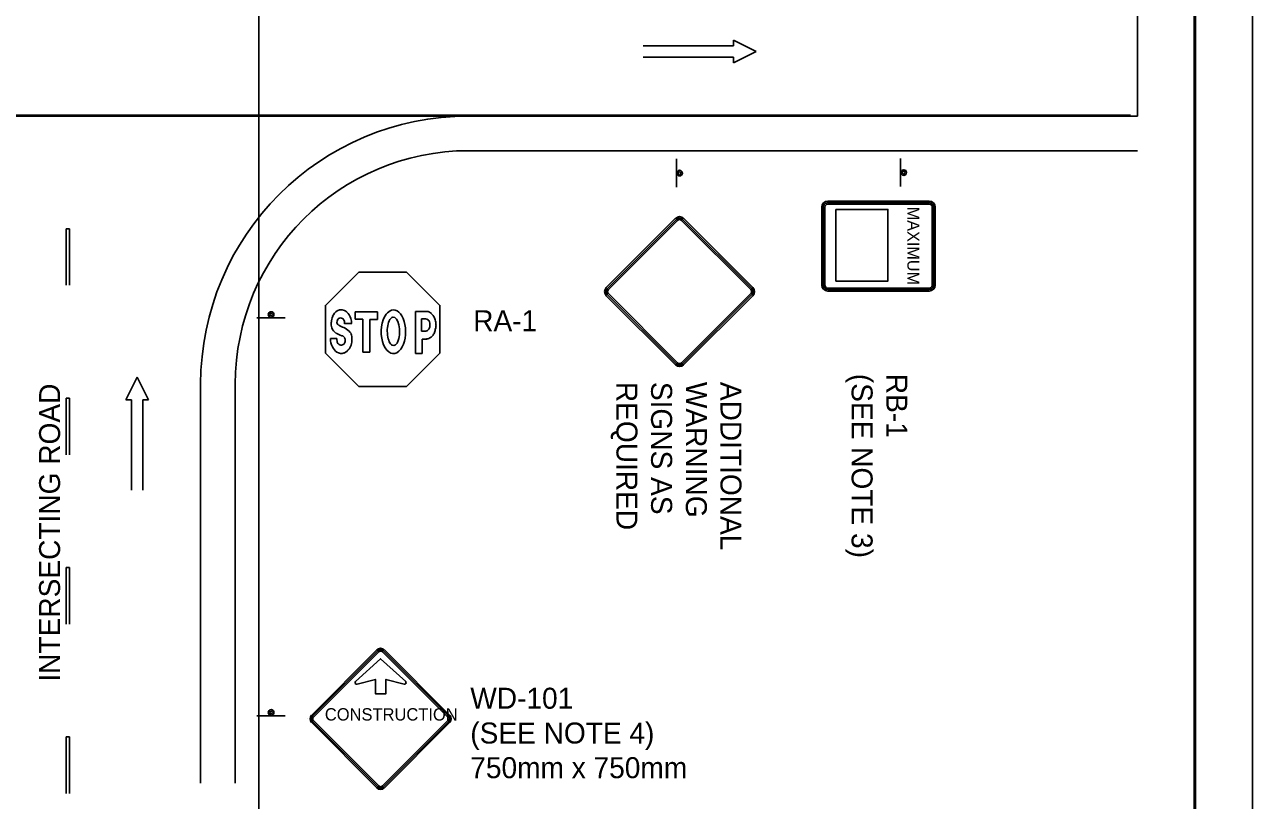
# Model space of a CAD drawing. Extents: x 1373 to 1583, y 130 to 399.
# Drawn here: x 1477.8 to 1583.1, y 197.4 to 263.9 of the extents above; entities that cross this region are included whole.
import ezdxf

# ---------------------------------------------------------------- set-up
doc = ezdxf.new("R2010")
doc.units = 0
for name, color, linetype in [('Level 10', 7, 'Continuous'), ('Level 17', 7, 'Continuous'), ('Level 18', 7, 'Continuous'), ('Level 2', 7, 'Continuous'), ('Level 60', 7, 'Continuous')]:
    doc.layers.add(name, color=color, linetype=linetype)

msp = doc.modelspace()

# ---------------------------------------------------------------- linework, layer by layer
at = {"layer": 'Level 10'}
for p, q in [((1497.88, 390.01), (1497.88, 138.3)), ((1538.57, 262.54), (1540.51, 261.58)), ((1538.57, 262.06), (1538.57, 262.54)), ((1530.83, 262.06), (1538.57, 262.06)), ((1538.57, 261.09), (1530.83, 261.09)), ((1540.51, 261.58), (1538.57, 260.61)), ((1538.57, 260.61), (1538.57, 261.09)), ((1572.59, 256.13), (1394.25, 256.13)), ((1573.19, 256.04), (1515.85, 256.04)), ((1573.19, 253.08), (1515.85, 253.08)), ((1506.12, 238.64), (1506.12, 239.27)), ((1506.12, 239.27), (1508.03, 239.27)), ((1508.03, 239.27), (1508.03, 238.62)), ((1509.38, 239.43), (1509.4, 239.43)), ((1511.29, 235.71), (1511.29, 239.3)), ((1511.29, 239.3), (1512.29, 239.3)), ((1505.83, 238.26), (1505.21, 238.26)), ((1506.78, 238.64), (1506.12, 238.64)), ((1506.78, 235.82), (1506.78, 238.64)), ((1508.03, 238.62), (1507.4, 238.62)), ((1507.4, 238.62), (1507.4, 235.82)), ((1509.35, 238.82), (1509.38, 238.82)), ((1511.81, 238.66), (1511.81, 237.61)), ((1512.2, 238.66), (1511.81, 238.66)), ((1512.2, 238.66), (1511.81, 238.66)), ((1511.81, 238.66), (1511.81, 237.61)), ((1504.01, 236.98), (1504.57, 236.98)), ((1511.81, 237.61), (1512.19, 237.61)), ((1511.81, 237.61), (1512.19, 237.61)), ((1512.24, 236.94), (1511.88, 236.93)), ((1511.88, 236.93), (1512.26, 236.93)), ((1511.88, 236.93), (1511.88, 235.71)), ((1504.18, 236.26), (1504.18, 236.27)), ((1507.4, 235.82), (1506.78, 235.82)), ((1511.88, 235.71), (1511.29, 235.71)), ((1486.47, 231.73), (1487.44, 233.66)), ((1487.44, 233.66), (1488.4, 231.73)), ((1492.88, 233.08), (1492.88, 198.88)), ((1495.85, 233.08), (1495.85, 198.88)), ((1486.95, 231.73), (1486.47, 231.73)), ((1486.95, 223.99), (1486.95, 231.73)), ((1488.4, 231.73), (1487.92, 231.73)), ((1487.92, 231.73), (1487.92, 223.99))]:
    msp.add_line(p, q, dxfattribs=at)
for points in [[(1573.19, 279.61), (1573.19, 256.04), (1394.01, 256.04), (1394.01, 279.61)], [(1513.4, 235.73), (1510.53, 232.87), (1506.45, 232.87), (1503.58, 235.73), (1503.58, 239.82), (1506.45, 242.68), (1510.53, 242.68), (1513.4, 239.82)]]:
    msp.add_lwpolyline(points, close=True, dxfattribs=at)
for centre, radius, start, end in [((1515.85, 233.08), 22.97, 90, 180), ((1515.85, 233.08), 20, 90, 180), ((1505.19, 238.44), 1.09, 123.3662, 155.6734), ((1504.94, 238.78), 0.665, 46.1369, 121.3987), ((1504.67, 238.41), 1.12, 14.564, 49.0063), ((1512.24, 238.71), 0.596, 44.8528, 85.0441), ((1512.05, 238.45), 0.915, 29.2241, 48.5308), ((1512.05, 238.45), 0.915, 29.2241, 48.5308), ((1505.42, 238.26), 1.34, 174.8171, 195.9183), ((1505.61, 238.31), 1.52, 157.7332, 177.1392), ((1504.87, 238.38), 0.302, 164.131, 238.1476), ((1504.91, 238.43), 0.331, 113.8064, 172.2407), ((1505.83, 239.9), 2.1, 237.9816, 250.979), ((1504.89, 238.4), 0.346, 47.3017, 109.0119), ((1504.72, 238.34), 0.506, 350.4412, 39.3244), ((1504.6, 236.56), 1.47, 46.2465, 67.9263), ((1504.27, 238.24), 1.55, 0.6952, 17.1452), ((1512.14, 238.32), 0.354, 35.1198, 79.3117), ((1512.14, 238.32), 0.354, 35.1198, 79.3117), ((1511.98, 238.21), 0.55, 8.6031, 34.217), ((1511.98, 238.21), 0.55, 8.6031, 34.217), ((1512.01, 238.07), 0.522, 326.5086, 357.0313), ((1512.01, 238.07), 0.522, 326.5086, 357.0313), ((1511.96, 238.14), 0.585, 350.3417, 15.2342), ((1511.96, 238.14), 0.585, 350.3417, 15.2342), ((1512.04, 238.36), 0.972, 13.0674, 33.762), ((1511.17, 238.07), 1.89, 3.3903, 15.6597), ((1511.54, 238.11), 1.52, 349.7521, 2.7916), ((1511.54, 238.11), 1.52, 349.7521, 2.7916), ((1505.88, 237.06), 1.88, 182.3841, 204.9519), ((1505.03, 238.22), 0.952, 200.4481, 235.1107), ((1507.47, 243.66), 6.9, 244.4624, 248.8312), ((1505.42, 236.97), 0.856, 179.0172, 193.5172), ((1504.87, 236.81), 0.435, 34.2083, 74.1552), ((1504.88, 236.85), 0.399, 352.5761, 30.4776), ((1507.6, 239.24), 2.57, 219.479, 223.4261), ((1504.33, 236.89), 1.53, 5.9097, 21.9865), ((1503.69, 236.89), 2.16, 351.247, 3.9864), ((1512.11, 238.01), 0.406, 281.9191, 325.7868), ((1512.11, 238.01), 0.406, 281.9191, 325.7868), ((1512.28, 237.15), 0.207, 259.7909, 293.5419), ((1512.1, 237.8), 0.882, 286.602, 299.8091), ((1512.28, 237.57), 0.597, 295.3838, 322.6188), ((1512.03, 237.85), 0.968, 318.2922, 338.6031), ((1512.03, 237.85), 0.968, 318.2922, 338.6031), ((1511.08, 238.23), 1.98, 338.3153, 348.6699), ((1505.36, 236.9), 1.34, 208.4154, 233.6553), ((1504.94, 236.31), 0.612, 232.0536, 292.7397), ((1505.01, 236.8), 0.43, 186.8728, 222.7449), ((1504.96, 236.84), 0.419, 230.6966, 271.4573), ((1504.93, 236.81), 0.388, 275.4374, 314.0625), ((1504.8, 236.64), 0.977, 293.1413, 324.9906), ((1504.76, 236.81), 0.516, 326.253, 358.7323), ((1504.2, 237.04), 1.7, 325.5092, 343.2894)]:
    msp.add_arc(centre, radius, start, end, dxfattribs=at)
for centre, major_axis, ratio, start_param, end_param in [((1509.41, 237.56), (-0.01, -1.87), 0.558644, 3.185857, 4.129398), ((1509.41, 237.56), (-0.01, -1.87), 0.558644, 0.656861, 3.168126), ((1509.41, 237.56), (-0.01, -1.87), 0.558644, 4.129576, 6.939747), ((1509.41, 237.6), (0.01, -1.22), 0.432619, 3.890436, 7.165085), ((1509.41, 237.6), (0.01, -1.22), 0.432619, 3.239639, 3.888884), ((1509.41, 237.6), (0.01, -1.22), 0.432619, 0.881967, 3.190734)]:
    msp.add_ellipse(centre, major_axis=major_axis, ratio=ratio, start_param=start_param, end_param=end_param, dxfattribs=at)
at = {"layer": 'Level 17'}
for p, q in [((1533.67, 252.38), (1533.67, 249.96)), ((1552.89, 252.41), (1552.89, 250)), ((1546.65, 248.75), (1555.35, 248.75)), ((1546.65, 248.62), (1555.35, 248.62)), ((1546.65, 248.5), (1555.35, 248.5)), ((1555.76, 248.47), (1555.76, 248.47)), ((1546.14, 241.57), (1546.14, 248.24)), ((1546.27, 241.57), (1546.27, 248.24)), ((1546.4, 241.57), (1546.4, 248.24)), ((1555.61, 248.24), (1555.61, 241.57)), ((1555.74, 248.24), (1555.74, 241.57)), ((1555.82, 248.36), (1555.81, 248.36)), ((1555.86, 248.24), (1555.86, 241.57)), ((1555.87, 248.24), (1555.86, 248.24)), ((1527.66, 241.35), (1533.59, 247.29)), ((1527.75, 241.27), (1533.68, 247.19)), ((1527.84, 241.18), (1533.77, 247.1)), ((1534.11, 247.1), (1540.04, 241.18)), ((1534.2, 247.19), (1540.13, 241.27)), ((1534.29, 247.29), (1540.21, 241.35)), ((1555.35, 241.31), (1546.65, 241.31)), ((1555.35, 241.18), (1546.65, 241.18)), ((1533.59, 234.73), (1527.66, 240.65)), ((1533.68, 234.81), (1527.75, 240.74)), ((1533.77, 234.9), (1527.84, 240.83)), ((1540.04, 240.83), (1534.11, 234.9)), ((1540.12, 240.74), (1534.2, 234.81)), ((1540.21, 240.65), (1534.29, 234.73)), ((1540.04, 240.83), (1540.04, 240.83)), ((1540.13, 240.74), (1540.12, 240.74)), ((1540.22, 240.65), (1540.21, 240.65)), ((1555.35, 241.05), (1546.65, 241.05)), ((1497.7, 238.76), (1500.12, 238.76)), ((1502.4, 204.71), (1508, 210.3)), ((1502.48, 204.62), (1508.08, 210.22)), ((1502.56, 204.54), (1508.17, 210.14)), ((1508.46, 210.14), (1514.06, 204.54)), ((1508.55, 210.22), (1514.15, 204.62)), ((1508.63, 210.3), (1514.23, 204.71)), ((1506.29, 207.36), (1506.29, 207.36)), ((1506.29, 207.36), (1506.29, 207.36)), ((1506.29, 207.36), (1506.29, 207.36)), ((1497.7, 204.66), (1500.12, 204.66)), ((1502.08, 204.39), (1502.08, 204.39)), ((1508.17, 198.64), (1502.56, 204.24)), ((1514.06, 204.24), (1508.46, 198.64)), ((1508, 198.47), (1502.4, 204.07)), ((1508.08, 198.56), (1502.48, 204.16)), ((1514.15, 204.16), (1508.55, 198.56)), ((1514.23, 204.07), (1508.63, 198.47))]:
    msp.add_line(p, q, dxfattribs=at)
msp.add_lwpolyline([(1547.35, 248.05), (1551.8, 248.05), (1551.8, 241.91), (1547.35, 241.91)], close=True, dxfattribs=at)
for points in [[(1506.17, 207.59), (1508.31, 209.54), (1510.46, 207.59)], [(1506.17, 207.59), (1508.31, 209.54), (1510.46, 207.59)], [(1506.17, 207.59), (1508.31, 209.54), (1510.46, 207.59)], [(1510.33, 207.36), (1508.76, 207.77), (1508.76, 206.54), (1507.87, 206.54), (1507.87, 207.77), (1506.29, 207.36)], [(1510.33, 207.36), (1508.76, 207.77), (1508.76, 206.54), (1507.87, 206.54), (1507.87, 207.77), (1506.29, 207.36)], [(1510.33, 207.36), (1508.76, 207.77), (1508.76, 206.54), (1507.87, 206.54), (1507.87, 207.77), (1506.29, 207.36)]]:
    msp.add_lwpolyline(points, dxfattribs=at)
for centre, radius in [((1533.95, 251.16), 0.242), ((1533.95, 251.16), 0.121), ((1553.16, 251.2), 0.242), ((1553.16, 251.2), 0.121), ((1498.92, 239.04), 0.242), ((1498.92, 239.04), 0.121), ((1498.92, 204.94), 0.242), ((1498.92, 204.94), 0.121)]:
    msp.add_circle(centre, radius, dxfattribs=at)
for centre, radius, start, end in [((1546.65, 248.24), 0.515, 90, 180), ((1546.65, 248.24), 0.386, 90, 180), ((1546.65, 248.24), 0.258, 90, 180), ((1555.35, 248.24), 0.515, 0, 90), ((1555.35, 248.24), 0.386, 0, 90), ((1555.35, 248.24), 0.258, 0, 90), ((1533.94, 246.93), 0.496, 45, 135), ((1533.94, 246.93), 0.371, 45, 135), ((1533.94, 246.93), 0.246, 45, 135), ((1528.01, 241), 0.496, 135, 225), ((1528.01, 241), 0.371, 135, 225), ((1528.01, 241), 0.246, 135, 225), ((1539.87, 241), 0.246, 315, 45), ((1539.87, 241), 0.371, 315, 45), ((1539.87, 241), 0.496, 315, 45), ((1546.65, 241.57), 0.515, 180, 270), ((1546.65, 241.57), 0.386, 180, 270), ((1546.65, 241.57), 0.258, 180, 270), ((1555.35, 241.57), 0.515, 270, 0), ((1555.35, 241.57), 0.386, 270, 0), ((1555.35, 241.57), 0.258, 270, 0), ((1533.94, 235.08), 0.371, 225, 315), ((1533.94, 235.08), 0.246, 225, 315), ((1533.94, 235.08), 0.496, 225, 315), ((1508.31, 209.99), 0.447, 45, 135), ((1508.31, 209.99), 0.329, 45, 135), ((1508.31, 209.99), 0.212, 45, 135), ((1506.26, 207.49), 0.134, 132.3048, 284.4075), ((1506.26, 207.49), 0.134, 132.3048, 284.4075), ((1506.26, 207.49), 0.134, 132.3048, 284.4075), ((1510.36, 207.49), 0.134, 255.5925, 47.6952), ((1510.36, 207.49), 0.134, 255.5925, 47.6952), ((1510.36, 207.49), 0.134, 255.5925, 47.6952), ((1502.71, 204.39), 0.447, 135, 225), ((1502.71, 204.39), 0.329, 135, 225), ((1502.71, 204.39), 0.212, 135, 225), ((1513.91, 204.39), 0.212, 315, 45), ((1513.91, 204.39), 0.329, 315, 45), ((1513.91, 204.39), 0.447, 315, 45), ((1508.31, 198.79), 0.447, 225, 315), ((1508.31, 198.79), 0.329, 225, 315), ((1508.31, 198.79), 0.212, 225, 315)]:
    msp.add_arc(centre, radius, start, end, dxfattribs=at)
at = {"layer": 'Level 2'}
for p, q in [((1481.35, 246.39), (1481.35, 241.55)), ((1481.64, 246.39), (1481.35, 246.39)), ((1481.64, 241.55), (1481.64, 246.39)), ((1481.35, 231.87), (1481.35, 227.03)), ((1481.64, 231.87), (1481.35, 231.87)), ((1481.64, 227.03), (1481.64, 231.87)), ((1481.35, 217.36), (1481.35, 212.52)), ((1481.64, 217.36), (1481.35, 217.36)), ((1481.64, 212.52), (1481.64, 217.36)), ((1481.35, 202.84), (1481.35, 198)), ((1481.64, 202.84), (1481.35, 202.84)), ((1481.64, 198), (1481.64, 202.84))]:
    msp.add_line(p, q, dxfattribs=at)
at = {"layer": 'Level 60'}
msp.add_line((1583.06, 129.98), (1583.06, 398.98), dxfattribs=at)
for points in [[(1383.77, 393.31), (1578.17, 393.31), (1578.17, 135.56), (1383.77, 135.56)], [(1391.18, 393.17), (1578.06, 393.17), (1578.06, 135.79), (1391.18, 135.79)]]:
    msp.add_lwpolyline(points, close=True, dxfattribs=at)

# ---------------------------------------------------------------- texts
at = {"layer": 'Level 10'}
msp.add_text('INTERSECTING ROAD', height=1.8, rotation=90, dxfattribs=at).set_placement((1480.83, 207.58))
at = {"layer": 'Level 17'}
for s, height, p in [('MAXIMUM', 1.039, (1553.47, 248.28)), ('REQUIRED', 1.8, (1528.53, 233.27)), ('SIGNS AS ', 1.8, (1531.5, 233.27)), ('WARNING ', 1.8, (1534.48, 233.27)), ('ADDITIONAL ', 1.7999, (1537.45, 233.27))]:
    msp.add_text(s, height=height, rotation=270, dxfattribs=at).set_placement(p)
for s, height, p in [('RA-1', 1.8, (1516.25, 237.61)), ('WD-101', 1.8, (1516, 205.26)), ('CONSTRUCTION', 1.0575, (1503.53, 204.25)), ('(SEE NOTE 4)', 1.8, (1516, 202.28)), ('750mm x 750mm', 1.8, (1516, 199.31))]:
    msp.add_text(s, height=height, dxfattribs=at).set_placement(p)
at = {"layer": 'Level 18'}
for s, p in [('(SEE NOTE 3)', (1548.69, 233.96)), ('RB-1', (1551.67, 233.96))]:
    msp.add_text(s, height=1.8, rotation=270, dxfattribs=at).set_placement(p)

doc.saveas('drawing.dxf')
